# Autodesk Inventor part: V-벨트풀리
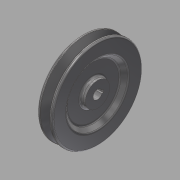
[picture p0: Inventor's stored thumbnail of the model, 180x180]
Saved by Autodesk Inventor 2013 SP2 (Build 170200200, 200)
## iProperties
Created: 2015-12
Part Number: V-벨트풀리
Document SubType Name: Modeling
Designer: mdu
Density: 8.08 g/cm^3
Material: 스테인리스강
Author: mdu
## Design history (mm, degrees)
sketch "스케치1"
  geometry: L1 (-10, 0)-(10, 0); L2 (-10, 0)-(-10, 16); L3 (-10, 16)-(-4, 16); L4 (-4, 16)-(-4, 35); L5 (-4, 35)-(-10, 41); L6 (-10, 41)-(-10, 59.5); L7 (-10, 59.5)-(-6.062, 59.5); L8 (-6.062, 59.5)-(-2.001, 47); L9 (-2.001, 47)-(2.001, 47); L10 (2.001, 47)-(6.062, 59.5); L11 (6.062, 59.5)-(10, 59.5); L12 (10, 59.5)-(10, 41); L13 (10, 41)-(4, 35); L14 (4, 35)-(4, 16); L15 (4, 16)-(10, 16); L16 (10, 16)-(10, 0); L17 (-4.6, 55)-(4.6, 55); 2 further points
  constraints: 34 end point, 7 parallel, 6 equal length, 5 collinear, 3 perpendicular, 2 point on line, 1 coincident, 1 horizontal, 1 midpoint
  dimensions: "d0" = 20 distance of L1.start L1.end; "d1" = 9.2 distance of L17.start L17.end; "d2" = 36 deg angle of L10 L8; "d3" = 4.5 distance between parallel lines of L7 L17; "d4" = 8 distance between parallel lines of L9 L17; "d6" = 110 diameter of L17 L1; "d7" = 32 diameter of L3 L1; "d8" = 82 diameter of L5.end L1; "d9" = 6 distance of L2.end L3.end; "d10" = 135 deg angle of L4 L5
revolve "회전1" sketch "스케치1" stored, may be unused: angle "d11" = 90 deg
fillet "모깎기1" dims "d12" = 2, "d13" = 0.5, "d14" = 1, "d15" = 3
sketch "스케치2"
  geometry: L1 (-2, 5.657)-(-2, 7.8); L2 (-2, 7.8)-(2, 7.8); L3 (2, 7.8)-(2, 5.657); A1 r 6 centre (0, 0) between (-2, 5.657) and (2, 5.657); 1 further point
  constraints: 6 end point, 2 parallel, 2 point on circle, 1 centre point, 1 coincident, 1 perpendicular, 1 vertical
  dimensions: "d16" = 12 diameter of A1; "d17" = 4 distance of L1.end L2.end; "d18" = 13.8 dimension on A1 L2 (computed from d16)
extrude "돌출1" cut sketch "스케치2" stored distance "d19" = 10; taper "d20" = 0 deg
node "솔리드1"
